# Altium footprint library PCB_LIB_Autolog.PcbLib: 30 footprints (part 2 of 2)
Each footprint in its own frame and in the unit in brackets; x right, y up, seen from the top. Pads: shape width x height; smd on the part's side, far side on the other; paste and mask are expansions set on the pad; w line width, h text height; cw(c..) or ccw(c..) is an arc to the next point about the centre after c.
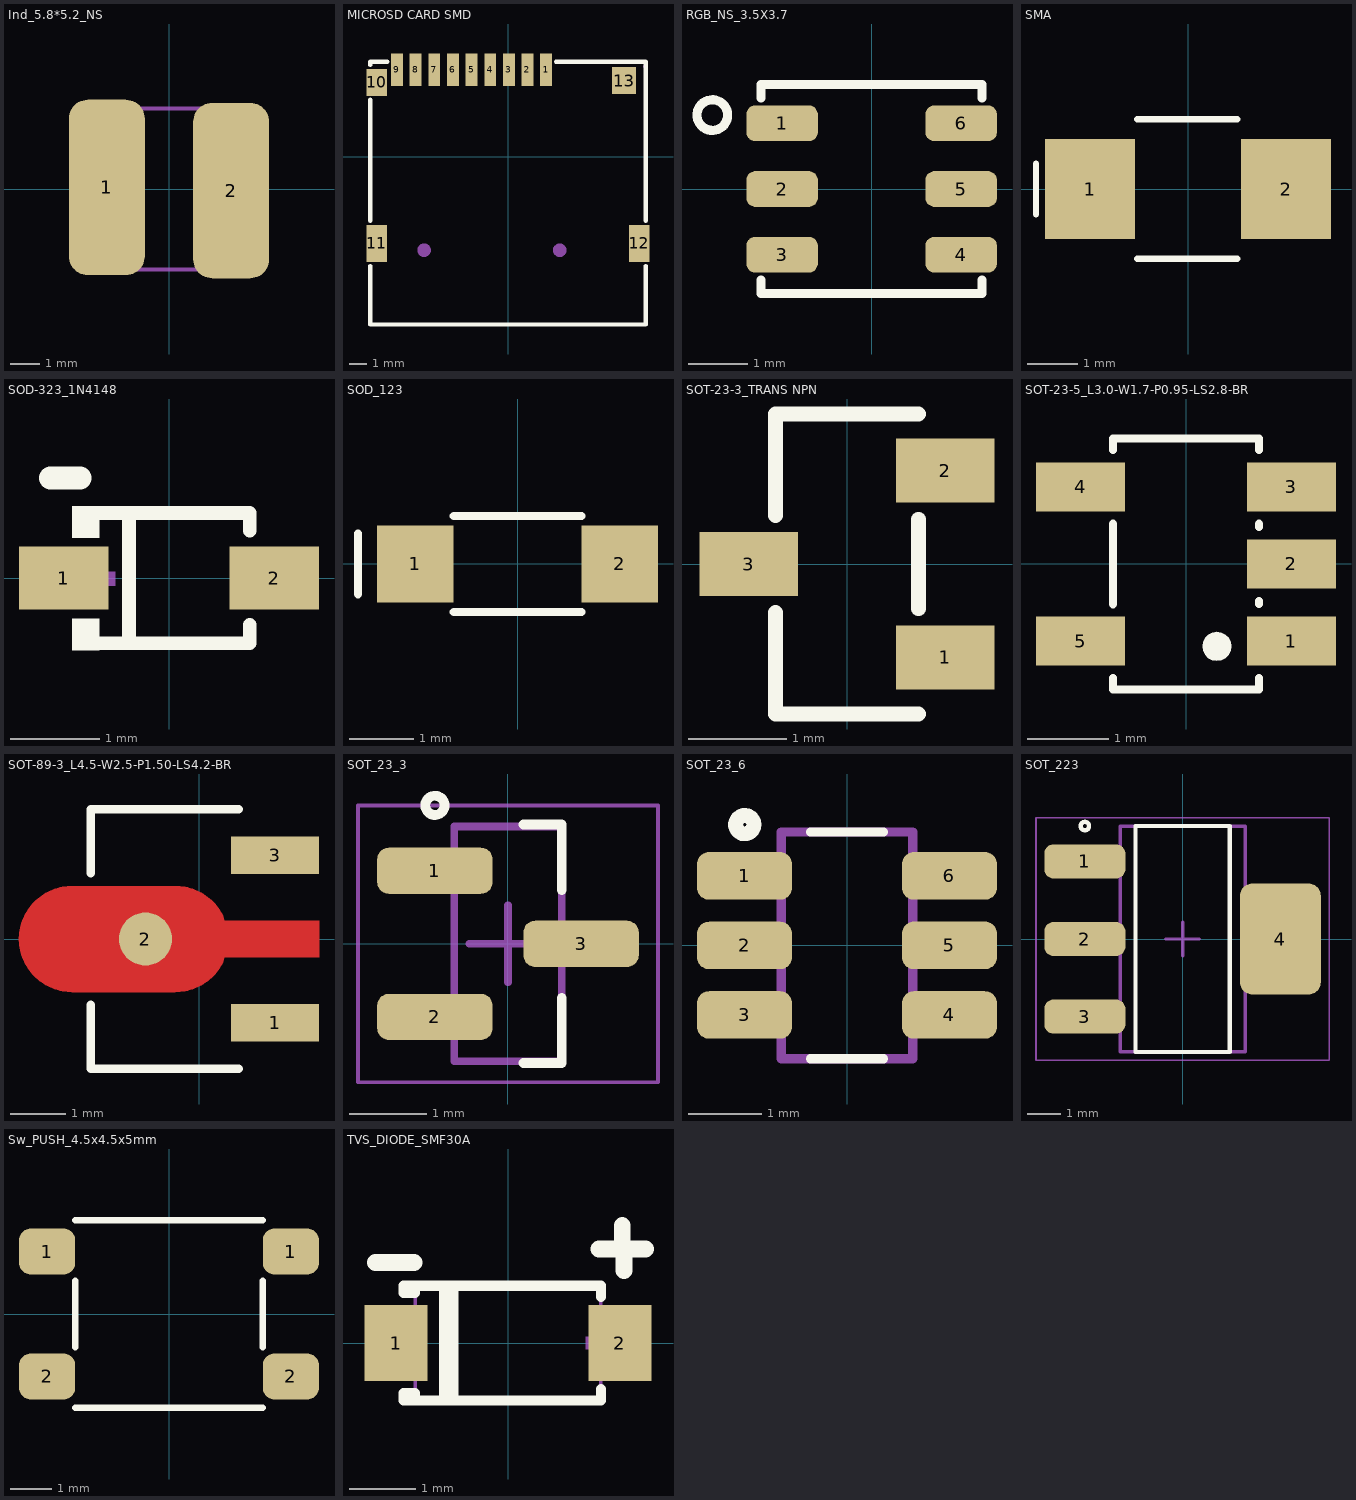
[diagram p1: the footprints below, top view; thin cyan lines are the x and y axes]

## Ind_5.8*5.2_NS [mm]
pads (2):
  rrect50% 2.6x6 smd: 1(-2.125,0.053) 2(2.125,-0.053)
Mechanical 1:
  lines w0.152: -3,-2.75 3,-2.75 3,2.75 -3,2.75 -3,-2.75
3D body: height 4.5, standoff 0, extent -3,-2.75 3,2.75

## MICROSD CARD SMD [mm]
pads (13):
  rect 0.7x1.9 smd: 1(2.25,5.125) 2(1.15,5.125) 3(0.05,5.125) 4(-1.05,5.125) 5(-2.15,5.125) 6(-3.25,5.125) 7(-4.35,5.125) 8(-5.45,5.125) 9(-6.55,5.125)
  rect 1.2x1.6 smd: 10(-7.75,4.375)
  rect 1.2x2.2 smd: 11(-7.75,-5.125) 12(7.75,-5.125)
  rect 1.4x1.6 smd: 13(6.85,4.475)
Top Overlay:
  lines w0.254: -8.128,-6.456 -8.128,-9.906 8.128,-9.906 8.128,-6.456 ; -8.128,-3.794 -8.128,3.344 ; -8.128,5.406 -8.128,5.588 -7.131,5.588 ; 2.831,5.588 8.128,5.588 8.128,-3.794
Mechanical 2:
  circle w0.4: c3.05,-5.527 r0.2
  circle w0.4: c-4.95,-5.525 r0.2
Mechanical 8:
  region: 8.11,5.312 8.11,5.287 8.075,5.252 8.025,5.252 7.99,5.287 7.99,5.312 7.99,5.336 8.025,5.371 8.075,5.371 8.11,5.336 8.11,5.312
Mechanical 9:
  region: 2.1,5.312 2.4,5.312 2.4,4.812 2.1,4.812
  region: 1,5.312 1.3,5.312 1.3,4.812 1,4.812
  region: -0.1,5.312 0.2,5.312 0.2,4.812 -0.1,4.812
  region: -1.2,5.312 -0.9,5.312 -0.9,4.812 -1.2,4.812
  region: -2.3,5.312 -2,5.312 -2,4.812 -2.3,4.812
  region: -3.4,5.312 -3.1,5.312 -3.1,4.812 -3.4,4.812
  region: -4.5,5.312 -4.2,5.312 -4.2,4.812 -4.5,4.812
  region: -5.6,5.312 -5.3,5.312 -5.3,4.812 -5.6,4.812
  region: -6.7,5.312 -6.4,5.312 -6.4,4.812 -6.7,4.812
3D body "MICROSD.STEP": height 1.9, standoff -0.55, extent -8.075,-9.405 8.025,5.595

## RGB_NS_3.5X3.7 [mm]
pads (6):
  rrect50% 1.2x0.6 smd: 1(-1.5,1.1) 2(-1.5,0) 3(-1.5,-1.1) 4(1.5,-1.1) 5(1.5,0) 6(1.5,1.1)
Top Overlay:
  circle w0.152: c-2.669,1.238 r0.257
  lines w0.152: -1.85,-1.524 -1.85,-1.75 1.85,-1.75 1.85,-1.524 ; -1.85,1.524 -1.85,1.75 1.85,1.75 1.85,1.524
3D body: height 1, standoff 0, extent -1.849,-1.744 1.849,1.751

## SMA [mm]
pads (2):
  rect 1.8x2 smd: 1(-1.965,0) 2(1.965,0)
Top Overlay:
  lines w0.127: -3.048,-0.508 -3.048,0.508 ; -1.016,-1.397 0.984,-1.397 ; -1.016,1.397 0.984,1.397
3D body "SMASeries_LTF.step": height 2.34, standoff 0, extent -2.642,-1.397 2.642,1.397

## SOD-323_1N4148 [mm]
pads (2):
  rect 1x0.7 smd: 1(-1.172,0) 2(1.172,0)
Top Overlay:
  region: -0.775,0.802 -0.775,0.45 -1.08,0.45 -1.08,0.802
  region: -0.775,-0.803 -0.775,-0.45 -1.08,-0.45 -1.08,-0.803
  lines w0.152: -0.851,-0.726 0.901,-0.726 0.901,-0.52 ; -0.851,0.726 0.901,0.726 0.901,0.53 ; -0.447,-0.726 -0.447,0.726
  lines w0.254: -1.321,1.118 -0.991,1.118
Mechanical 2:
  region: -1.225,0.07 -1.225,-0.086 -0.601,-0.086 -0.601,0.07
Mechanical 7:
  region: -0.815,0.16 -0.815,-0.16 -0.935,-0.16 -0.935,0.16
  region: 0.985,0.16 0.985,-0.16 0.865,-0.16 0.865,0.16
Mechanical 9:
  region: 1.275,0.16 1.275,-0.16 0.975,-0.16 0.975,0.16
3D body "sod-323f.stp": height 1.1, standoff 0.1, extent -1.225,-0.686 1.275,0.564

## SOD_123 [mm]
pads (2):
  rect 1.2x1.2 smd: 1(-1.6,0) 2(1.6,0)
Top Overlay:
  lines w0.127: -2.5,-0.475 -2.5,0.475 ; -1,-0.75 1,-0.75 ; -1,0.749 1,0.749
3D body "SOD123.step": height 1.28, standoff 0.01, extent -1.926,-0.8 1.774,0.8

## SOT-23-3_TRANS NPN [mm]
pads (3):
  rect 1x0.65 smd: 1(1,-0.95) 2(1,0.95) 3(-1,0)
Top Overlay:
  lines w0.152: -0.726,-0.495 -0.726,-1.526 0.726,-1.526 ; -0.726,0.495 -0.726,1.526 0.726,1.526 ; 0.726,-0.455 0.726,0.455
Mechanical 7:
  region: -0.91,-0.215 -0.91,0.215 -0.64,0.215 -0.64,-0.215
3D body "SMMBT3904LT3G.STEP": height 1.11, standoff 0, extent -1.175,-1.45 1.225,1.45

## SOT-23-5_L3.0-W1.7-P0.95-LS2.8-BR [mm]
pads (5):
  rect 1.1x0.6 smd: 1(1.3,-0.95) 2(1.3,0) 3(1.3,0.95) 4(-1.3,0.95) 5(-1.3,-0.95)
Top Overlay:
  region: 0.204,-1.016 0.212,-0.961 0.237,-0.911 0.276,-0.871 0.326,-0.846 0.381,-0.837 0.436,-0.846 0.486,-0.871 0.525,-0.911 0.55,-0.961 0.558,-1.016 0.55,-1.071 0.525,-1.121 0.486,-1.161 0.436,-1.186 0.381,-1.195 0.326,-1.186 0.276,-1.161 0.237,-1.121 0.212,-1.071 0.204,-1.016
  lines w0.1: -0.9,-1.404 -0.9,-1.55 0.9,-1.55 0.9,-1.404 ; -0.9,-0.496 -0.9,0.496 ; -0.9,1.404 -0.9,1.55 0.9,1.55 0.9,1.404 ; 0.9,-0.496 0.9,-0.454 ; 0.9,0.454 0.9,0.496
Mechanical 7:
  region: -0.96,-1.15 -0.96,-0.75 -0.79,-0.75 -0.79,-1.15
  region: -0.96,0.75 -0.96,1.15 -0.79,1.15 -0.79,0.75
3D body: height 1, standoff 0, extent -0.927,-1.499 0.876,1.549

## SOT-89-3_L4.5-W2.5-P1.50-LS4.2-BR [mm]
pads (3):
  rect 1.575x0.672 smd paste+0 mask+0.051: 1(1.356,-1.5) 3(1.356,1.5)
  round 0.95 smd: 2(-0.966,0)
Top Layer:
  region: -2.283,0.95 -0.429,0.95 -0.384,0.949 -0.34,0.946 -0.296,0.94 -0.252,0.933 -0.208,0.924 -0.165,0.912 -0.123,0.899 -0.081,0.884 -0.04,0.866 0,0.847 0.04,0.826 0.078,0.803 0.115,0.779 0.151,0.752 0.185,0.724 0.219,0.695 0.251,0.664 0.281,0.631 0.31,0.597 0.337,0.562 0.362,0.525 0.386,0.488 0.408,0.449 0.428,0.409 0.447,0.33 2.144,0.33 2.144,-0.33 0.447,-0.33 0.428,-0.409 0.408,-0.449 0.386,-0.488 0.362,-0.526 0.337,-0.562 0.31,-0.597 0.281,-0.631 0.251,-0.664 0.219,-0.695 0.185,-0.725 0.151,-0.753 0.115,-0.779 0.078,-0.804 0.04,-0.827 0,-0.848 -0.04,-0.867 -0.081,-0.884 -0.123,-0.899 -0.165,-0.913 -0.208,-0.924 -0.252,-0.934 -0.296,-0.941 -0.34,-0.946 -0.384,-0.949 -0.429,-0.95 -2.283,-0.95 -2.328,-0.949 -2.372,-0.946 -2.416,-0.941 -2.46,-0.934 -2.504,-0.924 -2.547,-0.913 -2.589,-0.899 -2.631,-0.884 -2.672,-0.867 -2.713,-0.848 -2.752,-0.827 -2.79,-0.804 -2.827,-0.779 -2.863,-0.753 -2.898,-0.725 -2.931,-0.695 -2.963,-0.664 -2.993,-0.631 -3.022,-0.597 -3.049,-0.562 -3.075,-0.526 -3.098,-0.488 -3.12,-0.449 -3.141,-0.409 -3.159,-0.369 -3.175,-0.327 -3.189,-0.285 -3.202,-0.242 -3.212,-0.199 -3.22,-0.155 -3.227,-0.111 -3.231,-0.067 -3.233,-0.022 -3.233,0.022 -3.231,0.067 -3.227,0.111 -3.22,0.155 -3.212,0.199 -3.202,0.242 -3.189,0.285 -3.175,0.327 -3.159,0.369 -3.141,0.409 -3.12,0.449 -3.098,0.488 -3.075,0.525 -3.049,0.562 -3.022,0.597 -2.993,0.631 -2.963,0.664 -2.931,0.695 -2.898,0.724 -2.863,0.752 -2.827,0.779 -2.79,0.803 -2.752,0.826 -2.713,0.847 -2.672,0.866 -2.631,0.884 -2.589,0.899 -2.547,0.912 -2.504,0.924 -2.46,0.933 -2.416,0.94 -2.372,0.946 -2.328,0.949
Top Overlay:
  lines w0.152: -1.95,-1.177 -1.95,-2.326 0.702,-2.326 ; -1.95,1.177 -1.95,2.326 0.702,2.326
3D body: height 1, standoff 0, extent -1.943,-2.337 1.092,2.337

## SOT_23_3 [mm]
pads (3):
  rrect50% 1.5x0.6 smd: 1(-0.95,0.95) 2(-0.95,-0.95) 3(0.95,0)
Top Overlay:
  circle w0.127: c-0.95,1.8 r0.125
  lines w0.127: 0.2,-1.55 0.7,-1.55 0.7,-0.7 ; 0.2,1.55 0.7,1.55 0.7,0.7
Mechanical 1:
  lines w0.1: -0.7,-1.525 0.7,-1.525 0.7,1.525 -0.7,1.525 -0.7,-1.525
Mechanical 15:
  lines w0.05: -1.95,-1.8 -1.95,1.8 1.95,1.8 1.95,-1.8 -1.95,-1.8
  lines w0.1: -0.5,0 0.5,0 ; 0,-0.5 0,0.5
3D body: height 1.12, standoff 0.01, extent -0.7,-1.525 0.7,1.525

## SOT_23_6 [mm]
height 1.45
pads (6):
  rrect50% 1.3x0.65 smd: 1(-1.4,0.95) 2(-1.4,0) 3(-1.4,-0.95) 4(1.4,-0.95) 5(1.4,0) 6(1.4,0.95)
Top Overlay:
  circle w0.203: c-1.397,1.651 r0.125
  lines w0.127: -0.5,-1.55 0.5,-1.55 ; -0.5,1.55 0.5,1.55
Mechanical 1:
  lines w0.127: -0.9,-1.55 -0.9,1.55 0.9,1.55 0.9,-1.55 -0.9,-1.55
3D body "SOT23-6-2.step": height 1.45, standoff 0, extent -1.501,-1.45 1.299,1.45

## SOT_223 [mm]
height 1.45
pads (4):
  rrect50% 2.4x1 smd: 1(-2.9,2.3) 2(-2.9,0) 3(-2.9,-2.3)
  rrect30% 2.4x3.3 smd: 4(2.9,0)
Top Overlay:
  circle w0.127: c-2.9,3.35 r0.125
  lines w0.127: -1.4,-3.35 -1.4,3.35 1.4,3.35 1.4,-3.35 -1.4,-3.35
Mechanical 1:
  lines w0.1: -1.855,-3.35 -1.855,3.35 1.855,3.35 1.855,-3.35 -1.855,-3.35
Mechanical 15:
  lines w0.05: -4.35,-3.6 -4.35,3.6 4.35,3.6 4.35,-3.6 -4.35,-3.6
  lines w0.1: -0.5,0 0.5,0 ; 0,-0.5 0,0.5
3D body: height 1.8, standoff 0.03, extent -1.855,-3.35 1.855,3.35

## Sw_PUSH_4.5x4.5x5mm [mm]
pads (4):
  rrect50% 1.35x1.1 smd: 1(-2.925,1.5) 1(2.925,1.5) 2(-2.925,-1.5) 2(2.925,-1.5)
Top Overlay:
  lines w0.152: -2.25,-2.25 2.25,-2.25 ; -2.25,-0.8 -2.25,0.8 ; -2.25,2.25 2.25,2.25 ; 2.25,-0.8 2.25,0.8
3D body: height 5, standoff 0, extent -1.22,-1.22 1.22,1.22
3D body: height 2.75, standoff 0, extent -2.25,-2.25 2.25,2.25

## TVS_DIODE_SMF30A [mm]
pads (2):
  rect 0.95x1.15 smd: 1(-1.692,0) 2(1.692,0)
Top Overlay:
  lines w0.152: -0.97,-0.866 -0.97,0.866 ; -0.827,-0.866 -0.827,0.866 ; 1.406,-0.698 1.406,-0.866 0.703,-0.866 -0.703,-0.866 -1.406,-0.866 ; 1.406,0.698 1.406,0.866 -1.406,0.866 ; -1.406,-0.866 -1.406,-0.755 -1.58,-0.755 -1.58,-0.866 -1.406,-0.866 ; -1.406,0.866 -1.406,0.755 -1.58,0.755 -1.58,0.866 -1.406,0.866
  lines w0.254: -2.007,1.219 -1.422,1.219 ; 1.372,1.422 2.083,1.422 ; 1.727,1.778 1.727,1.422 1.753,1.397 1.753,1.092
Mechanical 2:
  region: 1.935,0.098 1.935,-0.092 1.177,-0.092 1.177,0.098
Mechanical 6:
  lines w0.051: -1.4,-0.9 -1.4,0.9 ; 1.4,-0.9 1.4,0.9
3D body "SMF30A.STEP": height 1.55, standoff 0.25, extent -1.85,-0.889 1.85,0.911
